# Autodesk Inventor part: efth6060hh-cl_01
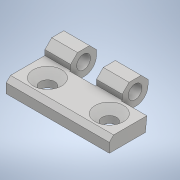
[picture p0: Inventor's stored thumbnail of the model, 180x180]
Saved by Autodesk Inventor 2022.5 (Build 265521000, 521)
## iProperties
Part Number: efth6060hh-cl_01
Material: 一般
Document SubType Name: Modeling
Designer: ImaoCorp
Density: 1 g/cm^3
Appearance: 既定
Author: ImaoCorp
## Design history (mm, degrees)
feature "efth6060hh-cl_01"
node "ソリッド1"
